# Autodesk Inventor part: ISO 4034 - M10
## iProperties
Comments: To add or edit properties for Autodesk Inventor files, use iProperties.
Created: 2004-08
Part Number: ISO 4034 - M10
Vendor: Autodesk Inc.
Document SubType Name: Modeling
Designer: John Blackburn
Material: Default
Description: Hex Nut
Standard: ISO 4034
Alert: To add or edit properties for Autodesk Inventor files, use iProperties.
Control State: 0
Master: False
Checked Out: False
Shininess: 64.0
Length Units: 11269
Angle Units: 11279
Time Units: 11290
Mass Units: 11283
Length Display Precision: 3
Angle Display Precision: 2
Compacted: True
EGR: 1
Density: 0.0
Volumn: 0.0
Area: 0.0
PropertySet Name: Model Information
Author: John Blackburn
Revision Number: 8
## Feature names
1. Body [Extrusion]
2. Chamfer1 [Revolution]
3. Thread [Hole]
4. Chamfer2
5. Chamfer3
